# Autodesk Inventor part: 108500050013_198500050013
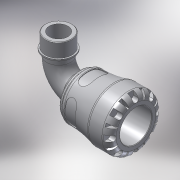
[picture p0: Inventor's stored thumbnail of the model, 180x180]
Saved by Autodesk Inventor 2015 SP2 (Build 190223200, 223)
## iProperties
Created: 2016-12
Part Number: 108500050013_198500050013
Material: PVC-Piping
Description: PLASSON 90° ELBOW WITH THREADED MALE OFFTAKE 50-1.1/4" SERIES 1
Document SubType Name: Modeling
Designer: KIM
Mass: 427.738 g
Surface Area: 637.61 cm^2
Volume: 305.527 cm^3
Density: 1.4 g/cm^3
Appearance: Smooth - White
Author: KIM
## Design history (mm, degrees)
derived "1085.ipt"
feature "Solid1::1085.ipt"
tag "TaggingFeature1"
body "Solid1"
other parameters: "d1" = 33.18, "d3" = 62.5, "d4" = 85, "d8" = 72.25, "d13" = 9, "d14" = 9, "d15" = 0, "d17" = 360 deg, "d19" = 8 deg, "d20" = 1, "d21" = 1, "d22" = 8 deg, "d24" = 0, "d26" = 360 deg, "d33" = 8.5, "d43" = 66.3, "d51" = 0.85, "d54" = 17.5, "d55" = 11, "d57" = 17.64, "d58" = 0, "d74" = 0, "d78" = 79, "d82" = 1, "d115" = 360 deg, "d207" = 90 deg, "d228" = 14.875, "d247" = 1.7, "d248" = 4.74, "d268" = 39.7375, "d269" = 4.74, "d270" = 122, "d276" = 41.91, "d277" = 22, "d278" = 46.101, "d279" = 68, "d280" = 24.2, "d281" = 6.2865, "d283" = 37.719, "d286" = 0, "d287" = 0, "d288" = 29.337, "d290" = 14.2905, "d292" = 30 deg, "E_" = 85, "l_" = 79, "A_" = 122, "A_1" = 68, "l_2" = 22, "R_" = 41.91, "d9" = 11.25, "d11" = 85, "d12" = 62.5, "d289" = 29.337
